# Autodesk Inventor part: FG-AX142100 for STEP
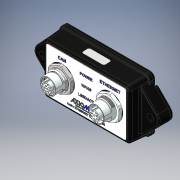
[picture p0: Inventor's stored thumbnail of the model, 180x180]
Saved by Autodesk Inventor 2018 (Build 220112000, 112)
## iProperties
Created: 2022-10
Part Number: FG-AX142100 for STEP
Material: Generic
Document SubType Name: Modeling
Designer: elondono
Density: 1 g/cm^3
Appearance: Default
Author: elondono
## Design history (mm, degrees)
derived "FG.iam"
body "Solid1"
node "MG.iam:1::PHO 1441817.iam:1::1441817 M12 8 pin.ipt:1"
node "MG.iam:1::PHO 1441817.iam:1::1441778 o ring.ipt:1"
node "MG.iam:1::PHO 1441817.iam:1::1441817 M12 back nut.ipt:1"
node "MG.iam:1::IJT-14010-01-R2 no chamfer.ipt:1"
node "MG.iam:1::IJT-14010-02-R1.ipt:1"
node "MG.iam:1::LBM-SERIAL-01-R2.ipt:1"
node "MG.iam:1::LBM-SERIAL-01-R2.ipt:2"
node "MG.iam:1::PLP5-2-125.ipt:1"
node "MG.iam:1::PLP5-2-125.ipt:2"
node "MG.iam:1::PLP5-2-125.ipt:3"
node "MG.iam:1::E-LOCTITE-E-30CL-50.ipt:1"
node "MG.iam:1::try.ipt:1"
node "MG.iam:1::PHO 1441833 LOCK NUT.ipt:1"
node "LBP-AX140900-01-R1.ipt:1"
node "LBM-AX142100-01-R1 for STEP.ipt:1"
